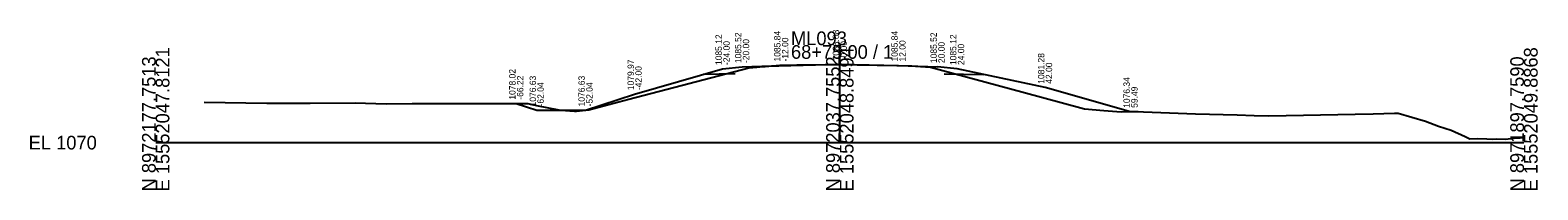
# Model space of a CAD drawing. Extents: x -26 to 14283, y -10 to 28.
# Drawn here: x 2974.3 to 3282.8, y -9.7 to 23.1 of the extents above; entities that cross this region are included whole.
import ezdxf

# ---------------------------------------------------------------- set-up
doc = ezdxf.new("R2010")
doc.units = 0
for name, color, linetype in [('Default', 7, 'Continuous'), ('dsn3DCenterLine', 7, 'Continuous'), ('dsn3DDitchBack', 7, 'Continuous'), ('dsn3DDitchFront', 7, 'Continuous'), ('dsn3DForeSlopeBarnRoofPoint', 7, 'Continuous'), ('dsn3DForeSlopeBreakLine', 7, 'Continuous'), ('dsn3DGroundLineIntercept', 7, 'Continuous'), ('dsn3DPavementTop', 7, 'Continuous'), ('dsn3DShoulderTop', 7, 'Continuous'), ('dsn3DSubgradeBreakLine', 7, 'Continuous'), ('dsn3DSubgradeHingePoint', 7, 'Continuous'), ('dsnGeopakCellCrossSection', 7, 'Continuous'), ('dsnXSEarthwork', 7, 'Continuous'), ('dsnXsExistingGround', 7, 'Continuous'), ('dsnXsShldrEarthFill', 7, 'Continuous'), ('dsnXsSideSlopes', 7, 'Continuous'), ('dsnXsTextOffsetElevFinGrd', 7, 'Continuous'), ('SurPointsNonDTM', 7, 'Continuous'), ('SurSurveyPoints', 7, 'Continuous')]:
    doc.layers.add(name, color=color, linetype=linetype)

msp = doc.modelspace()

# ---------------------------------------------------------------- linework, layer by layer
at = {"layer": 'Default'}
msp.add_lwpolyline([(3120, 15.52), (3140, 16.08), (3152, 15.84), (3160, 15.52)], dxfattribs=at)
at = {"layer": 'dsnGeopakCellCrossSection'}
for p, q in [((3140, 0), (3140, 20)), ((3000, 0), (3140, 0)), ((3140, 0), (3280, 0))]:
    msp.add_line(p, q, dxfattribs=at)
at = {"layer": 'dsnXSEarthwork'}
msp.add_lwpolyline([(3120, 15.52), (3128, 15.84), (3140, 16.08), (3152, 15.84), (3160, 15.52)], dxfattribs=at)
at = {"layer": 'dsnXsExistingGround'}
msp.add_lwpolyline([(3009.9, 8.31), (3022.74, 8.13), (3031.62, 8.13), (3040.83, 8.15), (3047.19, 7.98), (3052.5, 8.05), (3071.31, 8.03), (3075.85, 8.02), (3076.14, 8.01), (3077.92, 7.64), (3082.51, 6.7), (3082.91, 6.66), (3085.68, 6.43), (3086.11, 6.47), (3088.63, 6.71), (3096.84, 8.89), (3121.36, 15.36), (3123, 15.5), (3123.64, 15.55), (3124.75, 15.64), (3127.69, 15.89), (3131.22, 15.93), (3140.02, 16.05), (3143.57, 15.99), (3151.67, 15.84), (3154.15, 15.75), (3154.76, 15.73), (3155.45, 15.68), (3158.53, 15.45), (3177.24, 10.4), (3190.09, 6.96), (3194.01, 6.61), (3197.56, 6.29), (3200.21, 6.36), (3201.02, 6.38), (3202.15, 6.33), (3212.79, 5.89), (3221.32, 5.7), (3224.79, 5.55), (3227.8, 5.5), (3245.49, 5.84), (3249.14, 5.92), (3253.49, 6.02), (3254.28, 6.04), (3259.86, 4.4), (3262.52, 3.37), (3265.09, 2.54), (3267.96, 1.27), (3268.63, 0.91), (3268.89, 0.78), (3270.4, 0.82), (3272.37, 0.78), (3273.57, 0.72), (3274.31, 0.76), (3276.15, 0.74), (3278.61, 0.98), (3279.24, 1.01), (3279.83, 1.14), (3280, 1.17)], dxfattribs=at)
at = {"layer": 'dsnXsShldrEarthFill'}
for points in [[(3118.61, 14.13), (3112.01, 13.98)], [(3161.37, 14.14), (3169.35, 13.98)]]:
    msp.add_lwpolyline(points, dxfattribs=at)
at = {"layer": 'dsnXsSideSlopes'}
for points in [[(3073.78, 8.02), (3073.78, 8.02), (3077.96, 6.63), (3077.96, 6.63), (3087.96, 6.63), (3087.96, 6.63), (3098, 9.97), (3098, 9.97), (3116, 15.12), (3116, 15.12), (3120, 15.52)], [(3199.49, 6.34), (3199.49, 6.34), (3182, 11.28), (3164, 15.12), (3164, 15.12), (3164, 15.12), (3160, 15.52)]]:
    msp.add_lwpolyline(points, dxfattribs=at)
at = {"layer": 'SurPointsNonDTM'}
msp.add_lwpolyline([(3199.17, 6.39), (3200.17, 6.39)], dxfattribs=at)
at = {"layer": 'SurSurveyPoints'}
for points in [[(3280, 0.99), (3279.21, 0.99)], [(3279.74, 1.31), (3280, 1.31)]]:
    msp.add_lwpolyline(points, dxfattribs=at)

# ---------------------------------------------------------------- texts
msp.add_text('-', height=0.0001).set_placement((3000, 0))
at = {"layer": 'dsn3DCenterLine'}
msp.add_text('X', height=0.00781, dxfattribs=at).set_placement((3140, 16.07))
at = {"layer": 'dsn3DDitchBack'}
msp.add_text('X', height=0.00781, dxfattribs=at).set_placement((3077.95, 6.62))
at = {"layer": 'dsn3DDitchFront'}
msp.add_text('X', height=0.00781, dxfattribs=at).set_placement((3087.95, 6.62))
at = {"layer": 'dsn3DForeSlopeBarnRoofPoint'}
for p in [(3098, 9.97), (3182, 11.28)]:
    msp.add_text('X', height=0.00781, dxfattribs=at).set_placement(p)
at = {"layer": 'dsn3DForeSlopeBreakLine'}
for p in [(3116, 15.11), (3164, 15.11)]:
    msp.add_text('X', height=0.00781, dxfattribs=at).set_placement(p)
at = {"layer": 'dsn3DGroundLineIntercept'}
for p in [(3073.77, 8.02), (3199.49, 6.34)]:
    msp.add_text('X', height=0.00781, dxfattribs=at).set_placement(p)
at = {"layer": 'dsn3DPavementTop'}
for p in [(3128, 15.83), (3152, 15.83)]:
    msp.add_text('X', height=0.00781, dxfattribs=at).set_placement(p)
at = {"layer": 'dsn3DShoulderTop'}
for p in [(3120, 15.51), (3160, 15.51)]:
    msp.add_text('X', height=0.00781, dxfattribs=at).set_placement(p)
at = {"layer": 'dsn3DSubgradeBreakLine'}
for p in [(3128, 14.33), (3140, 14.57)]:
    msp.add_text('X', height=0.00781, dxfattribs=at).set_placement(p)
at = {"layer": 'dsn3DSubgradeHingePoint'}
for p in [(3112, 13.97), (3169.35, 13.97)]:
    msp.add_text('X', height=0.00781, dxfattribs=at).set_placement(p)
at = {"layer": 'dsnGeopakCellCrossSection'}
for s, p in [('ML093', (3130, 20)), ('68+75.00 / 1', (3130, 17.2)), ('EL 1070', (2974, -1.4))]:
    msp.add_text(s, height=2.8, dxfattribs=at).set_placement(p)
for s, p in [('E 15552047.8121', (3002.8, -10)), ('E 15552048.8494', (3142.8, -10)), ('E 15552049.8868', (3282.8, -10)), ('N 8972177.7513', (3000, -10)), ('N 8972037.7552', (3140, -10)), ('N 8971897.7590', (3280, -10))]:
    msp.add_text(s, height=2.8, rotation=90, dxfattribs=at).set_placement(p)
at = {"layer": 'dsnXsTextOffsetElevFinGrd'}
for s, p in [('1085.12', (3115.85, 15.92)), ('1085.52', (3119.85, 16.32)), ('1085.84', (3127.85, 16.64)), ('1085.84', (3127.85, 16.64)), ('1086.08', (3139.85, 16.88)), ('1085.84', (3151.85, 16.64)), ('1085.52', (3159.85, 16.32)), ('1085.12', (3163.85, 15.92)), ('-24.00', (3117.45, 15.92)), ('-20.00', (3121.45, 16.32)), ('-12.00', (3129.45, 16.64)), ('-12.00', (3129.45, 16.64)), ('-0.00', (3141.45, 16.88)), ('12.00', (3153.45, 16.64)), ('20.00', (3161.45, 16.32)), ('24.00', (3165.45, 15.92)), ('1079.97', (3097.85, 10.77)), ('-42.00', (3099.45, 10.77)), ('1081.28', (3181.85, 12.08)), ('42.00', (3183.45, 12.08)), ('1078.02', (3073.63, 8.82)), ('-66.22', (3075.23, 8.82)), ('1076.63', (3077.81, 7.43)), ('1076.63', (3087.81, 7.43)), ('1076.63', (3087.81, 7.43)), ('1076.34', (3199.34, 7.14)), ('1076.34', (3199.34, 7.14)), ('-62.04', (3079.41, 7.43)), ('-52.04', (3089.41, 7.43)), ('-52.04', (3089.41, 7.43)), ('59.49', (3200.94, 7.14)), ('59.49', (3200.94, 7.14))]:
    msp.add_text(s, height=1.3, rotation=90, dxfattribs=at).set_placement(p)

doc.saveas('drawing.dxf')
